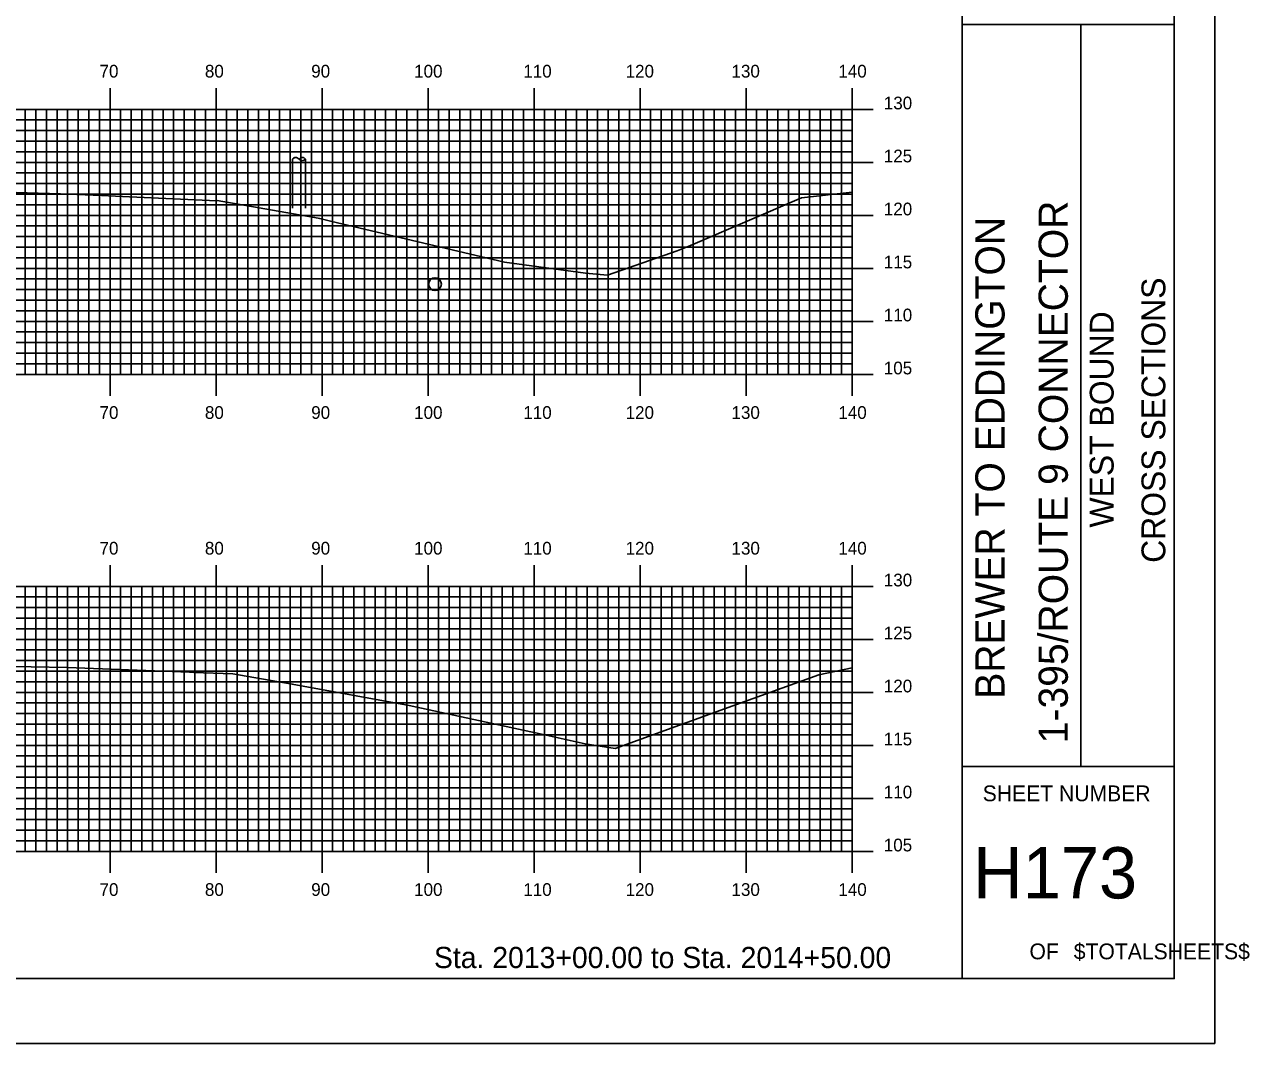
# Model space of a CAD drawing. Extents: x 854287 to 854631, y 366605 to 366825.
# Drawn here: x 854515 to 854630.5, y 366604.9 to 366701.1 of the extents above; entities that cross this region are included whole.
import ezdxf

# ---------------------------------------------------------------- set-up
doc = ezdxf.new("R2010")
doc.units = 0
for name, color, linetype in [('BORDER', 7, 'Continuous'), ('H_V ANNOTATION', 7, 'Continuous'), ('MAJOR', 7, 'Continuous'), ('MINOR', 7, 'Continuous'), ('PLOT BOUNDARY', 7, 'Continuous'), ('S_Drainage_Invert', 7, 'Continuous'), ('S_Roadway_Centerline', 7, 'Continuous'), ('S_Utilities_Pole_StreetLight', 7, 'Continuous')]:
    doc.layers.add(name, color=color, linetype=linetype)

msp = doc.modelspace()

# ---------------------------------------------------------------- linework, layer by layer
at = {"layer": 'BORDER'}
for p, q in [((854603.44, 366611.06), (854603.44, 366821.06)), ((854603.44, 366701.06), (854623.44, 366701.06)), ((854614.63, 366631.06), (854614.63, 366701.06)), ((854603.44, 366631.06), (854623.44, 366631.06))]:
    msp.add_line(p, q, dxfattribs=at)
msp.add_lwpolyline([(854303.44, 366611.06), (854623.44, 366611.06), (854623.44, 366821.06), (854303.44, 366821.06)], close=True, dxfattribs=at)
at = {"layer": 'MAJOR'}
for p, q in [((854523.04, 366695.06), (854523.04, 366693.06)), ((854533.04, 366695.06), (854533.04, 366693.06)), ((854543.04, 366695.06), (854543.04, 366693.06)), ((854553.04, 366695.06), (854553.04, 366693.06)), ((854563.04, 366695.06), (854563.04, 366693.06)), ((854573.04, 366695.06), (854573.04, 366693.06)), ((854583.04, 366695.06), (854583.04, 366693.06)), ((854593.04, 366695.06), (854593.04, 366693.06)), ((854313.04, 366693.06), (854593.04, 366693.06)), ((854313.04, 366693.06), (854593.04, 366693.06)), ((854523.04, 366668.06), (854523.04, 366693.06)), ((854533.04, 366668.06), (854533.04, 366693.06)), ((854543.04, 366668.06), (854543.04, 366693.06)), ((854553.04, 366668.06), (854553.04, 366693.06)), ((854563.04, 366668.06), (854563.04, 366693.06)), ((854573.04, 366668.06), (854573.04, 366693.06)), ((854583.04, 366668.06), (854583.04, 366693.06)), ((854595.05, 366693.06), (854591.04, 366693.06)), ((854593.04, 366668.06), (854593.04, 366693.06)), ((854593.04, 366668.06), (854593.04, 366693.06)), ((854313.04, 366688.06), (854593.04, 366688.06)), ((854595.05, 366688.06), (854591.04, 366688.06)), ((854313.04, 366683.06), (854593.04, 366683.06)), ((854595.05, 366683.06), (854591.04, 366683.06)), ((854313.04, 366678.06), (854593.04, 366678.06)), ((854595.05, 366678.06), (854591.04, 366678.06)), ((854313.04, 366673.06), (854593.04, 366673.06)), ((854595.05, 366673.06), (854591.04, 366673.06)), ((854313.04, 366668.06), (854593.04, 366668.06)), ((854313.04, 366668.06), (854593.04, 366668.06)), ((854523.04, 366666.05), (854523.04, 366668.06)), ((854533.04, 366666.05), (854533.04, 366668.06)), ((854543.04, 366666.05), (854543.04, 366668.06)), ((854553.04, 366666.05), (854553.04, 366668.06)), ((854563.04, 366666.05), (854563.04, 366668.06)), ((854573.04, 366666.05), (854573.04, 366668.06)), ((854583.04, 366666.05), (854583.04, 366668.06)), ((854595.05, 366668.06), (854591.04, 366668.06)), ((854593.04, 366666.05), (854593.04, 366668.06)), ((854523.04, 366650.06), (854523.04, 366648.06)), ((854533.04, 366650.06), (854533.04, 366648.06)), ((854543.04, 366650.06), (854543.04, 366648.06)), ((854553.04, 366650.06), (854553.04, 366648.06)), ((854563.04, 366650.06), (854563.04, 366648.06)), ((854573.04, 366650.06), (854573.04, 366648.06)), ((854583.04, 366650.06), (854583.04, 366648.06)), ((854593.04, 366650.06), (854593.04, 366648.06)), ((854313.04, 366648.06), (854593.04, 366648.06)), ((854313.04, 366648.06), (854593.04, 366648.06)), ((854523.04, 366623.06), (854523.04, 366648.06)), ((854533.04, 366623.06), (854533.04, 366648.06)), ((854543.04, 366623.06), (854543.04, 366648.06)), ((854553.04, 366623.06), (854553.04, 366648.06)), ((854563.04, 366623.06), (854563.04, 366648.06)), ((854573.04, 366623.06), (854573.04, 366648.06)), ((854583.04, 366623.06), (854583.04, 366648.06)), ((854595.05, 366648.06), (854591.04, 366648.06)), ((854593.04, 366623.06), (854593.04, 366648.06)), ((854593.04, 366623.06), (854593.04, 366648.06)), ((854313.04, 366643.06), (854593.04, 366643.06)), ((854595.05, 366643.06), (854591.04, 366643.06)), ((854313.04, 366638.06), (854593.04, 366638.06)), ((854595.05, 366638.06), (854591.04, 366638.06)), ((854313.04, 366633.06), (854593.04, 366633.06)), ((854595.05, 366633.06), (854591.04, 366633.06)), ((854313.04, 366628.06), (854593.04, 366628.06)), ((854595.05, 366628.06), (854591.04, 366628.06)), ((854313.04, 366623.06), (854593.04, 366623.06)), ((854313.04, 366623.06), (854593.04, 366623.06)), ((854523.04, 366621.05), (854523.04, 366623.06)), ((854533.04, 366621.05), (854533.04, 366623.06)), ((854543.04, 366621.05), (854543.04, 366623.06)), ((854553.04, 366621.05), (854553.04, 366623.06)), ((854563.04, 366621.05), (854563.04, 366623.06)), ((854573.04, 366621.05), (854573.04, 366623.06)), ((854583.04, 366621.05), (854583.04, 366623.06)), ((854595.05, 366623.06), (854591.04, 366623.06)), ((854593.04, 366621.05), (854593.04, 366623.06))]:
    msp.add_line(p, q, dxfattribs=at)
at = {"layer": 'MINOR'}
for p, q in [((854515.04, 366668.06), (854515.04, 366693.06)), ((854516.04, 366668.06), (854516.04, 366693.06)), ((854517.04, 366668.06), (854517.04, 366693.06)), ((854518.04, 366668.06), (854518.04, 366693.06)), ((854519.04, 366668.06), (854519.04, 366693.06)), ((854520.04, 366668.06), (854520.04, 366693.06)), ((854521.04, 366668.06), (854521.04, 366693.06)), ((854522.04, 366668.06), (854522.04, 366693.06)), ((854524.04, 366668.06), (854524.04, 366693.06)), ((854525.04, 366668.06), (854525.04, 366693.06)), ((854526.04, 366668.06), (854526.04, 366693.06)), ((854527.04, 366668.06), (854527.04, 366693.06)), ((854528.04, 366668.06), (854528.04, 366693.06)), ((854529.04, 366668.06), (854529.04, 366693.06)), ((854530.04, 366668.06), (854530.04, 366693.06)), ((854531.04, 366668.06), (854531.04, 366693.06)), ((854532.04, 366668.06), (854532.04, 366693.06)), ((854534.04, 366668.06), (854534.04, 366693.06)), ((854535.04, 366668.06), (854535.04, 366693.06)), ((854536.04, 366668.06), (854536.04, 366693.06)), ((854537.04, 366668.06), (854537.04, 366693.06)), ((854538.04, 366668.06), (854538.04, 366693.06)), ((854539.04, 366668.06), (854539.04, 366693.06)), ((854540.04, 366668.06), (854540.04, 366693.06)), ((854541.04, 366668.06), (854541.04, 366693.06)), ((854542.04, 366668.06), (854542.04, 366693.06)), ((854544.04, 366668.06), (854544.04, 366693.06)), ((854545.04, 366668.06), (854545.04, 366693.06)), ((854546.04, 366668.06), (854546.04, 366693.06)), ((854547.04, 366668.06), (854547.04, 366693.06)), ((854548.04, 366668.06), (854548.04, 366693.06)), ((854549.04, 366668.06), (854549.04, 366693.06)), ((854550.04, 366668.06), (854550.04, 366693.06)), ((854551.04, 366668.06), (854551.04, 366693.06)), ((854552.04, 366668.06), (854552.04, 366693.06)), ((854554.04, 366668.06), (854554.04, 366693.06)), ((854555.04, 366668.06), (854555.04, 366693.06)), ((854556.04, 366668.06), (854556.04, 366693.06)), ((854557.04, 366668.06), (854557.04, 366693.06)), ((854558.04, 366668.06), (854558.04, 366693.06)), ((854559.04, 366668.06), (854559.04, 366693.06)), ((854560.04, 366668.06), (854560.04, 366693.06)), ((854561.04, 366668.06), (854561.04, 366693.06)), ((854562.04, 366668.06), (854562.04, 366693.06)), ((854564.04, 366668.06), (854564.04, 366693.06)), ((854565.04, 366668.06), (854565.04, 366693.06)), ((854566.04, 366668.06), (854566.04, 366693.06)), ((854567.04, 366668.06), (854567.04, 366693.06)), ((854568.04, 366668.06), (854568.04, 366693.06)), ((854569.04, 366668.06), (854569.04, 366693.06)), ((854570.04, 366668.06), (854570.04, 366693.06)), ((854571.04, 366668.06), (854571.04, 366693.06)), ((854572.04, 366668.06), (854572.04, 366693.06)), ((854574.04, 366668.06), (854574.04, 366693.06)), ((854575.04, 366668.06), (854575.04, 366693.06)), ((854576.04, 366668.06), (854576.04, 366693.06)), ((854577.04, 366668.06), (854577.04, 366693.06)), ((854578.04, 366668.06), (854578.04, 366693.06)), ((854579.04, 366668.06), (854579.04, 366693.06)), ((854580.04, 366668.06), (854580.04, 366693.06)), ((854581.04, 366668.06), (854581.04, 366693.06)), ((854582.04, 366668.06), (854582.04, 366693.06)), ((854584.04, 366668.06), (854584.04, 366693.06)), ((854585.04, 366668.06), (854585.04, 366693.06)), ((854586.04, 366668.06), (854586.04, 366693.06)), ((854587.04, 366668.06), (854587.04, 366693.06)), ((854588.04, 366668.06), (854588.04, 366693.06)), ((854589.04, 366668.06), (854589.04, 366693.06)), ((854590.04, 366668.06), (854590.04, 366693.06)), ((854591.04, 366668.06), (854591.04, 366693.06)), ((854592.04, 366668.06), (854592.04, 366693.06)), ((854313.04, 366692.06), (854593.04, 366692.06)), ((854593.04, 366692.06), (854591.04, 366692.06)), ((854313.04, 366691.06), (854593.04, 366691.06)), ((854593.04, 366691.06), (854591.04, 366691.06)), ((854313.04, 366690.06), (854593.04, 366690.06)), ((854593.04, 366690.06), (854591.04, 366690.06)), ((854313.04, 366689.06), (854593.04, 366689.06)), ((854593.04, 366689.06), (854591.04, 366689.06)), ((854313.04, 366687.06), (854593.04, 366687.06)), ((854593.04, 366687.06), (854591.04, 366687.06)), ((854313.04, 366686.06), (854593.04, 366686.06)), ((854593.04, 366686.06), (854591.04, 366686.06)), ((854313.04, 366685.06), (854593.04, 366685.06)), ((854593.04, 366685.06), (854591.04, 366685.06)), ((854313.04, 366684.06), (854593.04, 366684.06)), ((854593.04, 366684.06), (854591.04, 366684.06)), ((854313.04, 366682.06), (854593.04, 366682.06)), ((854313.04, 366681.06), (854593.04, 366681.06)), ((854593.04, 366682.06), (854591.04, 366682.06)), ((854593.04, 366681.06), (854591.04, 366681.06)), ((854313.04, 366680.06), (854593.04, 366680.06)), ((854593.04, 366680.06), (854591.04, 366680.06)), ((854313.04, 366679.06), (854593.04, 366679.06)), ((854593.04, 366679.06), (854591.04, 366679.06)), ((854313.04, 366677.06), (854593.04, 366677.06)), ((854593.04, 366677.06), (854591.04, 366677.06)), ((854313.04, 366676.06), (854593.04, 366676.06)), ((854593.04, 366676.06), (854591.04, 366676.06)), ((854313.04, 366675.06), (854593.04, 366675.06)), ((854593.04, 366675.06), (854591.04, 366675.06)), ((854313.04, 366674.06), (854593.04, 366674.06)), ((854593.04, 366674.06), (854591.04, 366674.06)), ((854313.04, 366672.06), (854593.04, 366672.06)), ((854593.04, 366672.06), (854591.04, 366672.06)), ((854313.04, 366671.06), (854593.04, 366671.06)), ((854593.04, 366671.06), (854591.04, 366671.06)), ((854313.04, 366670.06), (854593.04, 366670.06)), ((854593.04, 366670.06), (854591.04, 366670.06)), ((854313.04, 366669.06), (854593.04, 366669.06)), ((854593.04, 366669.06), (854591.04, 366669.06)), ((854515.04, 366623.06), (854515.04, 366648.06)), ((854516.04, 366623.06), (854516.04, 366648.06)), ((854517.04, 366623.06), (854517.04, 366648.06)), ((854518.04, 366623.06), (854518.04, 366648.06)), ((854519.04, 366623.06), (854519.04, 366648.06)), ((854520.04, 366623.06), (854520.04, 366648.06)), ((854521.04, 366623.06), (854521.04, 366648.06)), ((854522.04, 366623.06), (854522.04, 366648.06)), ((854524.04, 366623.06), (854524.04, 366648.06)), ((854525.04, 366623.06), (854525.04, 366648.06)), ((854526.04, 366623.06), (854526.04, 366648.06)), ((854527.04, 366623.06), (854527.04, 366648.06)), ((854528.04, 366623.06), (854528.04, 366648.06)), ((854529.04, 366623.06), (854529.04, 366648.06)), ((854530.04, 366623.06), (854530.04, 366648.06)), ((854531.04, 366623.06), (854531.04, 366648.06)), ((854532.04, 366623.06), (854532.04, 366648.06)), ((854534.04, 366623.06), (854534.04, 366648.06)), ((854535.04, 366623.06), (854535.04, 366648.06)), ((854536.04, 366623.06), (854536.04, 366648.06)), ((854537.04, 366623.06), (854537.04, 366648.06)), ((854538.04, 366623.06), (854538.04, 366648.06)), ((854539.04, 366623.06), (854539.04, 366648.06)), ((854540.04, 366623.06), (854540.04, 366648.06)), ((854541.04, 366623.06), (854541.04, 366648.06)), ((854542.04, 366623.06), (854542.04, 366648.06)), ((854544.04, 366623.06), (854544.04, 366648.06)), ((854545.04, 366623.06), (854545.04, 366648.06)), ((854546.04, 366623.06), (854546.04, 366648.06)), ((854547.04, 366623.06), (854547.04, 366648.06)), ((854548.04, 366623.06), (854548.04, 366648.06)), ((854549.04, 366623.06), (854549.04, 366648.06)), ((854550.04, 366623.06), (854550.04, 366648.06)), ((854551.04, 366623.06), (854551.04, 366648.06)), ((854552.04, 366623.06), (854552.04, 366648.06)), ((854554.04, 366623.06), (854554.04, 366648.06)), ((854555.04, 366623.06), (854555.04, 366648.06)), ((854556.04, 366623.06), (854556.04, 366648.06)), ((854557.04, 366623.06), (854557.04, 366648.06)), ((854558.04, 366623.06), (854558.04, 366648.06)), ((854559.04, 366623.06), (854559.04, 366648.06)), ((854560.04, 366623.06), (854560.04, 366648.06)), ((854561.04, 366623.06), (854561.04, 366648.06)), ((854562.04, 366623.06), (854562.04, 366648.06)), ((854564.04, 366623.06), (854564.04, 366648.06)), ((854565.04, 366623.06), (854565.04, 366648.06)), ((854566.04, 366623.06), (854566.04, 366648.06)), ((854567.04, 366623.06), (854567.04, 366648.06)), ((854568.04, 366623.06), (854568.04, 366648.06)), ((854569.04, 366623.06), (854569.04, 366648.06)), ((854570.04, 366623.06), (854570.04, 366648.06)), ((854571.04, 366623.06), (854571.04, 366648.06)), ((854572.04, 366623.06), (854572.04, 366648.06)), ((854574.04, 366623.06), (854574.04, 366648.06)), ((854575.04, 366623.06), (854575.04, 366648.06)), ((854576.04, 366623.06), (854576.04, 366648.06)), ((854577.04, 366623.06), (854577.04, 366648.06)), ((854578.04, 366623.06), (854578.04, 366648.06)), ((854579.04, 366623.06), (854579.04, 366648.06)), ((854580.04, 366623.06), (854580.04, 366648.06)), ((854581.04, 366623.06), (854581.04, 366648.06)), ((854582.04, 366623.06), (854582.04, 366648.06)), ((854584.04, 366623.06), (854584.04, 366648.06)), ((854585.04, 366623.06), (854585.04, 366648.06)), ((854586.04, 366623.06), (854586.04, 366648.06)), ((854587.04, 366623.06), (854587.04, 366648.06)), ((854588.04, 366623.06), (854588.04, 366648.06)), ((854589.04, 366623.06), (854589.04, 366648.06)), ((854590.04, 366623.06), (854590.04, 366648.06)), ((854591.04, 366623.06), (854591.04, 366648.06)), ((854592.04, 366623.06), (854592.04, 366648.06)), ((854313.04, 366647.06), (854593.04, 366647.06)), ((854593.04, 366647.06), (854591.04, 366647.06)), ((854313.04, 366646.06), (854593.04, 366646.06)), ((854593.04, 366646.06), (854591.04, 366646.06)), ((854313.04, 366645.06), (854593.04, 366645.06)), ((854313.04, 366644.06), (854593.04, 366644.06)), ((854593.04, 366645.06), (854591.04, 366645.06)), ((854593.04, 366644.06), (854591.04, 366644.06)), ((854313.04, 366642.06), (854593.04, 366642.06)), ((854593.04, 366642.06), (854591.04, 366642.06)), ((854313.04, 366641.06), (854593.04, 366641.06)), ((854593.04, 366641.06), (854591.04, 366641.06)), ((854313.04, 366640.06), (854593.04, 366640.06)), ((854593.04, 366640.06), (854591.04, 366640.06)), ((854313.04, 366639.06), (854593.04, 366639.06)), ((854593.04, 366639.06), (854591.04, 366639.06)), ((854313.04, 366637.06), (854593.04, 366637.06)), ((854313.04, 366636.06), (854593.04, 366636.06)), ((854593.04, 366637.06), (854591.04, 366637.06)), ((854593.04, 366636.06), (854591.04, 366636.06)), ((854313.04, 366635.06), (854593.04, 366635.06)), ((854593.04, 366635.06), (854591.04, 366635.06)), ((854313.04, 366634.06), (854593.04, 366634.06)), ((854593.04, 366634.06), (854591.04, 366634.06)), ((854313.04, 366632.06), (854593.04, 366632.06)), ((854593.04, 366632.06), (854591.04, 366632.06)), ((854313.04, 366631.06), (854593.04, 366631.06)), ((854593.04, 366631.06), (854591.04, 366631.06)), ((854313.04, 366630.06), (854593.04, 366630.06)), ((854313.04, 366629.06), (854593.04, 366629.06)), ((854593.04, 366630.06), (854591.04, 366630.06)), ((854593.04, 366629.06), (854591.04, 366629.06)), ((854313.04, 366627.06), (854593.04, 366627.06)), ((854593.04, 366627.06), (854591.04, 366627.06)), ((854313.04, 366626.06), (854593.04, 366626.06)), ((854593.04, 366626.06), (854591.04, 366626.06)), ((854313.04, 366625.06), (854593.04, 366625.06)), ((854593.04, 366625.06), (854591.04, 366625.06)), ((854313.04, 366624.06), (854593.04, 366624.06)), ((854593.04, 366624.06), (854591.04, 366624.06))]:
    msp.add_line(p, q, dxfattribs=at)
at = {"layer": 'PLOT BOUNDARY'}
msp.add_lwpolyline([(854287.26, 366604.94), (854627.26, 366604.94), (854627.26, 366824.94), (854287.26, 366824.94)], close=True, dxfattribs=at)
at = {"layer": 'S_Drainage_Invert'}
msp.add_circle((854553.7, 366676.57), 0.6, dxfattribs=at)
at = {"layer": 'S_Roadway_Centerline'}
for points in [[(854514.19, 366685.21), (854518.36, 366685.08), (854522.25, 366684.93), (854524.89, 366684.81), (854533.1, 366684.42), (854533.14, 366684.46), (854542.33, 366682.87), (854542.82, 366682.75), (854543.83, 366682.52), (854560.26, 366678.64), (854567.9, 366677.61), (854569.96, 366677.41), (854576.54, 366679.72), (854577.8, 366680.21), (854588.27, 366684.7), (854593.04, 366685.24)], [(854513.43, 366640.5), (854515.6, 366640.47), (854519.03, 366640.4), (854530.55, 366639.96), (854530.95, 366639.94), (854534.62, 366639.82), (854540.23, 366638.85), (854551.25, 366636.83), (854563.89, 366634.09), (854567.88, 366633.2), (854570.7, 366632.76), (854581, 366636.52), (854589.92, 366639.72), (854593.04, 366640.37)]]:
    msp.add_lwpolyline(points, dxfattribs=at)
at = {"layer": 'S_Utilities_Pole_StreetLight'}
for p, q in [((854540.24, 366688.37), (854540.4, 366688.48)), ((854540.24, 366683.75), (854540.24, 366688.37)), ((854540.71, 366688.48), (854540.87, 366688.37)), ((854541.02, 366688.48), (854540.87, 366688.37)), ((854540.87, 366688.37), (854541.02, 366688.26)), ((854541.49, 366688.37), (854541.34, 366688.48)), ((854541.34, 366688.26), (854541.49, 366688.37)), ((854541.49, 366683.75), (854541.49, 366688.37))]:
    msp.add_line(p, q, dxfattribs=at)
for centre, start, end in [((854540.55, 366688.26), 90, 125.2644), ((854540.55, 366688.26), 54.7356, 90), ((854541.18, 366688.26), 90, 125.2644), ((854541.18, 366688.48), 234.7356, 270), ((854541.18, 366688.26), 54.7356, 90), ((854541.18, 366688.48), 270, 305.2644)]:
    msp.add_arc(centre, 0.271, start, end, dxfattribs=at)

# ---------------------------------------------------------------- texts
at = {"layer": 'BORDER'}
for s, height, p in [('1-395/ROUTE 9 CONNECTOR', 2.7557, (854613.4, 366633.26)), ('BREWER TO EDDINGTON', 2.7557, (854607.43, 366637.46)), ('CROSS SECTIONS', 2.25, (854622.6, 366650.28)), ('WEST BOUND', 2.25, (854617.72, 366653.61))]:
    msp.add_text(s, height=height, rotation=90, dxfattribs=at).set_placement(p)
for s, height, p in [('SHEET NUMBER', 1.4905, (854605.37, 366627.79)), ('H173', 4.839, (854604.47, 366618.62)), ('OF', 1.491, (854609.78, 366612.88)), ('$TOTALSHEETS$', 1.4905, (854613.96, 366612.88))]:
    msp.add_text(s, height=height, dxfattribs=at).set_placement(p)
at = {"layer": 'H_V ANNOTATION'}
for s, height, p in [('70', 1.2, (854522.05, 366696.06)), ('80', 1.2, (854531.99, 366696.06)), ('90', 1.2, (854542.02, 366696.06)), ('100', 1.2, (854551.73, 366696.06)), ('110', 1.2, (854562.03, 366696.06)), ('120', 1.2, (854571.68, 366696.06)), ('130', 1.2, (854581.67, 366696.06)), ('140', 1.2, (854591.75, 366696.06)), ('130', 1.2, (854596.04, 366693.06)), ('125', 1.2, (854596.04, 366688.06)), ('120', 1.2, (854596.04, 366683.06)), ('115', 1.2, (854596.04, 366678.06)), ('110', 1.2, (854596.04, 366673.06)), ('105', 1.2, (854596.04, 366668.06)), ('70', 1.2, (854522.05, 366663.86)), ('80', 1.2, (854531.99, 366663.86)), ('90', 1.2, (854542.02, 366663.86)), ('100', 1.2, (854551.73, 366663.86)), ('110', 1.2, (854562.03, 366663.86)), ('120', 1.2, (854571.68, 366663.86)), ('130', 1.2, (854581.67, 366663.86)), ('140', 1.2, (854591.75, 366663.86)), ('70', 1.2, (854522.05, 366651.06)), ('80', 1.2, (854531.99, 366651.06)), ('90', 1.2, (854542.02, 366651.06)), ('100', 1.2, (854551.73, 366651.06)), ('110', 1.2, (854562.03, 366651.06)), ('120', 1.2, (854571.68, 366651.06)), ('130', 1.2, (854581.67, 366651.06)), ('140', 1.2, (854591.75, 366651.06)), ('130', 1.2, (854596.04, 366648.06)), ('125', 1.2, (854596.04, 366643.06)), ('120', 1.2, (854596.04, 366638.06)), ('115', 1.2, (854596.04, 366633.06)), ('110', 1.2, (854596.04, 366628.06)), ('105', 1.2, (854596.04, 366623.06)), ('70', 1.2, (854522.05, 366618.86)), ('80', 1.2, (854531.99, 366618.86)), ('90', 1.2, (854542.02, 366618.86)), ('100', 1.2, (854551.73, 366618.86)), ('110', 1.2, (854562.03, 366618.86)), ('120', 1.2, (854571.68, 366618.86)), ('130', 1.2, (854581.67, 366618.86)), ('140', 1.2, (854591.75, 366618.86)), ('Sta. 2013+00.00 to Sta. 2014+50.00', 2.0004, (854553.6, 366612.05))]:
    msp.add_text(s, height=height, dxfattribs=at).set_placement(p)

doc.saveas('drawing.dxf')
